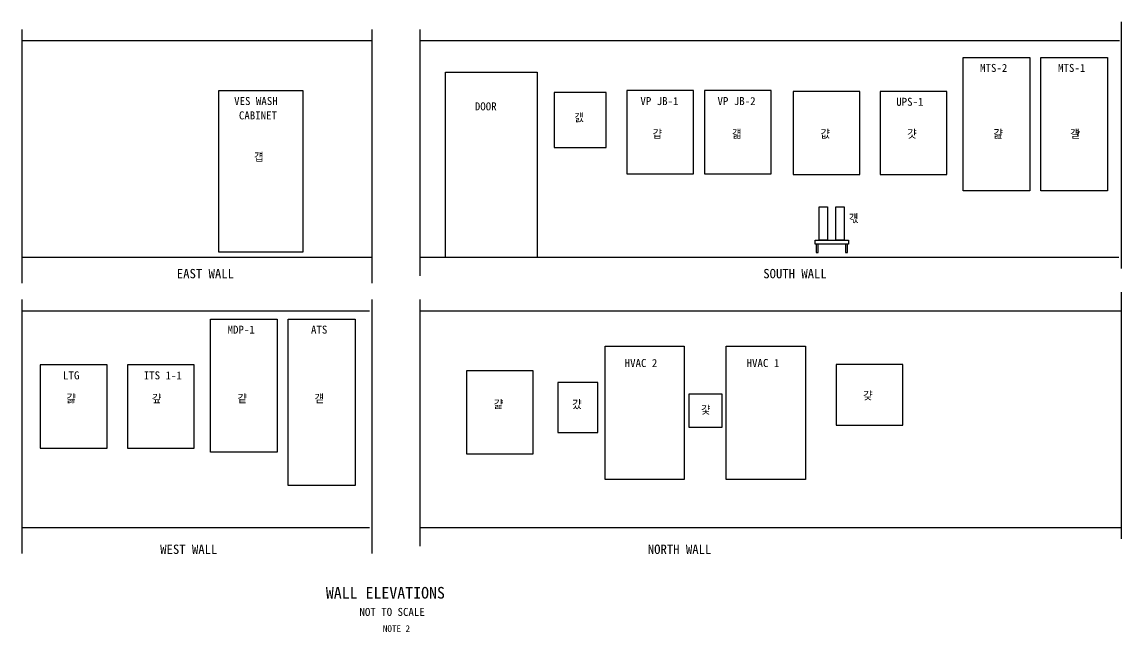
# Model space of a CAD drawing. Extents: x 2.8 to 35.8, y -2.3 to 16.
import ezdxf

# ---------------------------------------------------------------- set-up
doc = ezdxf.new("R2010")
doc.units = 0
for name, color, linetype in [('HS_Dimensions_and_Text', 7, 'Continuous'), ('HS_Electrical_Devices', 7, 'Continuous'), ('PDF_Geometry', 7, 'Continuous')]:
    doc.layers.add(name, color=color, linetype=linetype)

msp = doc.modelspace()

# ---------------------------------------------------------------- linework, layer by layer
at = {"layer": 'HS_Electrical_Devices'}
for p, q in [((35.783, 16.033), (35.783, 8.633)), ((2.817, 15.811), (2.817, 8.194)), ((13.311, 15.811), (13.311, 8.194)), ((14.75, 15.811), (14.75, 8.411)), ((13.311, 15.466), (2.817, 15.466)), ((35.739, 15.466), (14.75, 15.466)), ((13.311, 8.966), (2.817, 8.966)), ((35.722, 8.966), (14.75, 8.966)), ((35.783, 7.922), (35.783, 0.522)), ((2.817, 7.7), (2.817, 0.083)), ((13.311, 7.7), (13.311, 0.083)), ((14.75, 7.7), (14.75, 0.3)), ((13.244, 7.35), (2.817, 7.35)), ((35.783, 7.35), (14.75, 7.35)), ((13.244, 0.85), (2.817, 0.85)), ((35.783, 0.85), (14.75, 0.85))]:
    msp.add_line(p, q, dxfattribs=at)
for points in [[(31.044, 14.966), (33.044, 14.966), (33.044, 10.966), (31.044, 10.966)], [(33.378, 14.966), (35.378, 14.966), (35.378, 10.966), (33.378, 10.966)], [(15.517, 14.522), (18.272, 14.522), (18.272, 8.966), (15.517, 8.966)], [(8.722, 13.972), (11.244, 13.972), (11.244, 9.122), (8.722, 9.122)], [(18.778, 12.261), (20.344, 12.261), (20.344, 13.916), (18.778, 13.916)], [(20.961, 11.472), (22.961, 11.472), (22.961, 13.972), (20.961, 13.972)], [(23.294, 11.472), (25.294, 11.472), (25.294, 13.972), (23.294, 13.972)], [(25.95, 11.45), (27.95, 11.45), (27.95, 13.95), (25.95, 13.95)], [(28.561, 11.45), (30.561, 11.45), (30.561, 13.95), (28.561, 13.95)], [(26.983, 9.483), (26.733, 9.483), (26.733, 10.483), (26.983, 10.483)], [(27.483, 9.483), (27.233, 9.483), (27.233, 10.483), (27.483, 10.483)], [(26.606, 9.483), (27.606, 9.483), (27.606, 9.361), (26.606, 9.361)], [(26.7, 9.361), (26.639, 9.361), (26.639, 9.111), (26.7, 9.111)], [(27.578, 9.361), (27.517, 9.361), (27.517, 9.111), (27.578, 9.111)], [(8.472, 7.116), (10.472, 7.116), (10.472, 3.116), (8.472, 3.116)], [(10.806, 7.116), (12.806, 7.116), (12.806, 2.116), (10.806, 2.116)], [(20.311, 6.3), (22.683, 6.3), (22.683, 2.3), (20.311, 2.3)], [(23.944, 6.3), (26.317, 6.3), (26.317, 2.3), (23.944, 2.3)], [(3.367, 3.244), (5.367, 3.244), (5.367, 5.744), (3.367, 5.744)], [(5.983, 3.244), (7.983, 3.244), (7.983, 5.744), (5.983, 5.744)], [(27.239, 3.928), (29.239, 3.928), (29.239, 5.75), (27.239, 5.75)], [(16.15, 3.066), (18.15, 3.066), (18.15, 5.566), (16.15, 5.566)], [(18.889, 3.711), (20.089, 3.711), (20.089, 5.211), (18.889, 5.211)], [(22.822, 3.866), (23.822, 3.866), (23.822, 4.866), (22.822, 4.866)]]:
    msp.add_lwpolyline(points, close=True, dxfattribs=at)
at = {"layer": 'PDF_Geometry'}
msp.add_open_spline([(34.472, 12.644), (34.506, 12.694), (34.528, 12.733), (34.539, 12.75)], degree=2, dxfattribs=at)

# ---------------------------------------------------------------- texts
at = {"layer": 'HS_Dimensions_and_Text'}
for s, height, p in [('MTS-2', 0.24, (31.556, 14.533)), ('MTS-1', 0.24, (33.895, 14.533)), ('VES WASH', 0.24, (9.18, 13.541)), ('DOOR', 0.24, (16.401, 13.38)), ('VP JB-1', 0.24, (21.367, 13.539)), ('VP JB-2', 0.24, (23.679, 13.539)), ('UPS-1', 0.24, (29.041, 13.517)), ('CABINET', 0.24, (9.323, 13.109)), ('걠', 0.24, (19.384, 13.046)), ('걉', 0.24, (21.733, 12.554)), ('걟', 0.24, (24.113, 12.554)), ('걊', 0.24, (26.77, 12.554)), ('걋', 0.24, (29.368, 12.554)), ('걆', 0.24, (31.958, 12.554)), ('걜', 0.24, (34.258, 12.554)), ('걥', 0.24, (9.776, 11.86)), ('걗', 0.24, (27.62, 10.019)), ('EAST WALL', 0.28, (7.461, 8.34)), ('SOUTH WALL', 0.28, (25.052, 8.34)), ('MDP-1', 0.24, (8.984, 6.678)), ('ATS', 0.24, (11.486, 6.678)), ('HVAC 2', 0.24, (20.895, 5.676)), ('HVAC 1', 0.24, (24.552, 5.676)), ('LTG', 0.24, (4.049, 5.305)), ('ITS 1-1', 0.24, (6.469, 5.305)), ('걎', 0.24, (28.044, 4.7)), ('걇', 0.24, (4.15, 4.612)), ('걒', 0.24, (6.713, 4.612)), ('걑', 0.24, (9.281, 4.612)), ('걛', 0.24, (11.589, 4.612)), ('걅', 0.24, (16.968, 4.436)), ('걌', 0.24, (19.321, 4.434)), ('걏', 0.24, (23.183, 4.273)), ('WEST WALL', 0.28, (6.962, 0.066)), ('NORTH WALL', 0.28, (21.589, 0.066)), ('WALL ELEVATIONS', 0.35, (11.931, -1.275)), ('NOT TO SCALE', 0.24, (12.94, -1.795)), ('NOTE 2', 0.2, (13.642, -2.275))]:
    msp.add_text(s, height=height, dxfattribs=at).set_placement(p)

doc.saveas('drawing.dxf')
